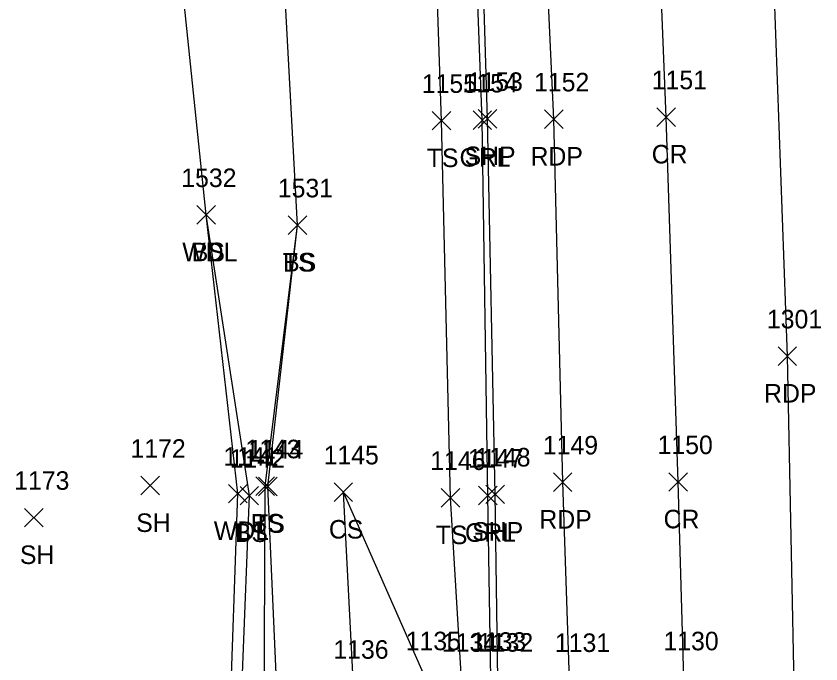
# Model space of a CAD drawing. Extents: x 1618262 to 1622220, y 273782 to 283685.
# Drawn here: x 1621992.5 to 1622079.3, y 282748.6 to 282818.4 of the extents above; entities that cross this region are included whole.
import ezdxf

# ---------------------------------------------------------------- set-up
doc = ezdxf.new("R2010")
doc.units = 0
for name, color, linetype in [('L_A', 7, 'Continuous'), ('L_I', 7, 'Continuous'), ('L_TIC', 7, 'Continuous'), ('LAWA', 7, 'Continuous'), ('LELB', 7, 'Continuous'), ('P_A', 7, 'Continuous'), ('P_I', 7, 'Continuous'), ('P_TIC', 7, 'Continuous'), ('PET', 7, 'Continuous'), ('PRC', 7, 'Continuous'), ('PSP', 7, 'Continuous'), ('R_A', 7, 'Continuous'), ('R_I', 7, 'Continuous'), ('R_TIC', 7, 'Continuous'), ('RGR', 7, 'Continuous')]:
    doc.layers.add(name, color=color, linetype=linetype)

msp = doc.modelspace()

# ---------------------------------------------------------------- linework, layer by layer
at = {"layer": 'L_TIC'}
for points in [[(1622037.366, 282806.145), (1622039.366, 282808.145)], [(1622039.366, 282806.145), (1622037.366, 282808.145)], [(1622012.003, 282795.989), (1622014.003, 282797.989)], [(1622014.003, 282795.989), (1622012.003, 282797.989)], [(1622012.003, 282795.989), (1622014.003, 282797.989)], [(1622014.003, 282795.989), (1622012.003, 282797.989)], [(1622021.846, 282794.877), (1622023.846, 282796.877)], [(1622023.846, 282794.877), (1622021.846, 282796.877)], [(1622021.846, 282794.877), (1622023.846, 282796.877)], [(1622023.846, 282794.877), (1622021.846, 282796.877)], [(1622005.964, 282766.79), (1622007.964, 282768.79)], [(1622007.964, 282766.79), (1622005.964, 282768.79)], [(1622018.347, 282766.736), (1622020.347, 282768.736)], [(1622020.347, 282766.736), (1622018.347, 282768.736)], [(1622018.651, 282766.692), (1622020.651, 282768.692)], [(1622020.651, 282766.692), (1622018.651, 282768.692)], [(1622026.782, 282766.08), (1622028.782, 282768.08)], [(1622028.782, 282766.08), (1622026.782, 282768.08)], [(1622026.782, 282766.08), (1622028.782, 282768.08)], [(1622028.782, 282766.08), (1622026.782, 282768.08)], [(1622015.402, 282765.923), (1622017.402, 282767.923)], [(1622017.402, 282765.923), (1622015.402, 282767.923)], [(1622016.648, 282765.711), (1622018.648, 282767.711)], [(1622018.648, 282765.711), (1622016.648, 282767.711)], [(1622038.334, 282765.475), (1622040.334, 282767.475)], [(1622040.334, 282765.475), (1622038.334, 282767.475)], [(1621993.426, 282763.336), (1621995.426, 282765.336)], [(1621995.426, 282763.336), (1621993.426, 282765.336)]]:
    msp.add_lwpolyline(points, dxfattribs=at)
at = {"layer": 'LAWA'}
msp.add_lwpolyline([(1622012.261, 282719.262), (1622015.512, 282741.117), (1622016.402, 282766.923), (1622013.003, 282796.989), (1622009.949, 282826.463), (1622001.868, 282858.825)], dxfattribs=at)
at = {"layer": 'LELB'}
for points in [[(1622031.53, 282480.209), (1622034.92, 282519.516), (1622036.308, 282559.668), (1622038.549, 282600.481), (1622040.575, 282634.794), (1622041.384, 282671.626), (1622041.057, 282708.261), (1622040.536, 282746.865), (1622039.334, 282766.475), (1622038.366, 282807.145), (1622036.997, 282847.689), (1622035.465, 282881.364), (1622030.123, 282906.905), (1622032.201, 282930.97)], [(1622011.792, 282703.523), (1622017.803, 282718.897), (1622019.25, 282742.062), (1622019.347, 282767.736), (1622022.846, 282795.877), (1622021.207, 282825.793), (1622021.001, 282858.668), (1622021.577, 282889.835), (1622019.372, 282916.251), (1622019.074, 282930.132)], [(1622006.83, 282701.587), (1622009.972, 282709.565), (1622013.354, 282718.948), (1622016.651, 282741.117), (1622017.648, 282766.711), (1622013.003, 282796.989)], [(1622011.792, 282703.523), (1622019.526, 282719.135), (1622020.798, 282741.845), (1622019.651, 282767.692), (1622022.846, 282795.877)], [(1622038.036, 282634.62), (1622038.492, 282672.044), (1622038.146, 282708.503), (1622036.634, 282747.032), (1622027.782, 282767.08)], [(1622029.212, 282715.273), (1622028.888, 282746.116), (1622027.782, 282767.08)]]:
    msp.add_lwpolyline(points, dxfattribs=at)
at = {"layer": 'P_TIC'}
for points in [[(1622042.312, 282806.356), (1622044.312, 282808.356)], [(1622044.312, 282806.356), (1622042.312, 282808.356)], [(1622049.471, 282806.305), (1622051.471, 282808.305)], [(1622051.471, 282806.305), (1622049.471, 282808.305)], [(1622061.59, 282806.537), (1622063.59, 282808.537)], [(1622063.59, 282806.537), (1622061.59, 282808.537)], [(1622074.649, 282780.747), (1622076.649, 282782.747)], [(1622076.649, 282780.747), (1622074.649, 282782.747)], [(1622050.427, 282767.15), (1622052.427, 282769.15)], [(1622052.427, 282767.15), (1622050.427, 282769.15)], [(1622062.87, 282767.185), (1622064.87, 282769.185)], [(1622064.87, 282767.185), (1622062.87, 282769.185)], [(1622043.138, 282765.852), (1622045.138, 282767.852)], [(1622045.138, 282765.852), (1622043.138, 282767.852)]]:
    msp.add_lwpolyline(points, dxfattribs=at)
at = {"layer": 'PET'}
for points in [[(1622055.389, 282357.789), (1622060.735, 282405.546), (1622064, 282439.097), (1622067.385, 282476.749), (1622069.453, 282501.975), (1622071.171, 282531.215), (1622072.586, 282558.991), (1622074.383, 282609.306), (1622075.404, 282650.493), (1622076.38, 282682.885), (1622076.73, 282709.495), (1622076.466, 282742.794), (1622075.649, 282781.747), (1622073.854, 282831.38), (1622072.41, 282861.117), (1622070.969, 282880.709), (1622069.108, 282909.864), (1622067.074, 282934.336)], [(1622031.404, 282363.078), (1622036.529, 282409.612), (1622039.656, 282443.455), (1622042.912, 282478.81), (1622045.922, 282518.248), (1622048.156, 282558.34), (1622049.907, 282599.505), (1622051.114, 282634.143), (1622051.904, 282670.586), (1622052.331, 282709.809), (1622052.148, 282746.848), (1622051.427, 282768.15), (1622050.471, 282807.305), (1622048.588, 282847.854), (1622046.49, 282883.042), (1622043.219, 282932.276)]]:
    msp.add_lwpolyline(points, dxfattribs=at)
at = {"layer": 'PRC'}
msp.add_lwpolyline([(1622043.286, 282360.387), (1622048.896, 282407.643), (1622051.69, 282440.973), (1622055.31, 282477.626), (1622057.865, 282516.742), (1622059.99, 282557.513), (1622061.585, 282597.203), (1622062.841, 282633.199), (1622063.878, 282668.538), (1622064.406, 282708.38), (1622064.503, 282747.028), (1622063.87, 282768.185), (1622062.59, 282807.537), (1622060.956, 282848.034), (1622058.907, 282883.676), (1622055.26, 282933.108)], dxfattribs=at)
at = {"layer": 'PSP'}
msp.add_lwpolyline([(1622024.53, 282364.695), (1622029.224, 282410.341), (1622032.133, 282444.404), (1622034.721, 282480.169), (1622038.065, 282518.937), (1622040.189, 282559.981), (1622041.775, 282599.797), (1622043.576, 282635.077), (1622043.931, 282671.705), (1622044.179, 282709.624), (1622044.427, 282746.882), (1622044.138, 282766.852), (1622043.312, 282807.356), (1622042.106, 282847.846), (1622040.006, 282882.115), (1622036.278, 282931.352)], dxfattribs=at)
at = {"layer": 'R_TIC'}
for points in [[(1622041.763, 282806.193), (1622043.763, 282808.193)], [(1622043.763, 282806.193), (1622041.763, 282808.193)], [(1622042.35, 282765.727), (1622044.35, 282767.727)], [(1622044.35, 282765.727), (1622042.35, 282767.727)]]:
    msp.add_lwpolyline(points, dxfattribs=at)
at = {"layer": 'RGR'}
msp.add_lwpolyline([(1622023.476, 282364.894), (1622028.185, 282410.184), (1622031.232, 282444.188), (1622033.737, 282480.242), (1622036.802, 282518.899), (1622039.036, 282560.065), (1622040.978, 282599.772), (1622042.921, 282635.171), (1622043.063, 282671.763), (1622043.615, 282709.363), (1622043.681, 282746.97), (1622043.35, 282766.727), (1622042.763, 282807.193), (1622041.251, 282847.718), (1622039.436, 282882.181), (1622035.129, 282907.981)], dxfattribs=at)

# ---------------------------------------------------------------- texts
at = {"layer": 'L_A'}
for s, p in [('TS', (1622036.776, 282802.145)), ('WDL', (1622010.42, 282791.989)), ('BS', (1622011.444, 282791.989)), ('TS', (1622021.255, 282790.877)), ('BS', (1622021.287, 282790.877)), ('SH', (1622005.452, 282762.79)), ('BS', (1622017.788, 282762.736)), ('TS', (1622018.061, 282762.692)), ('WDL', (1622013.819, 282761.923)), ('BS', (1622016.089, 282761.711)), ('CS', (1622026.223, 282762.08)), ('CS', (1622026.223, 282762.08)), ('TS', (1622037.743, 282761.475)), ('SH', (1621992.915, 282759.336))]:
    msp.add_text(s, height=2, dxfattribs=at).set_placement(p)
at = {"layer": 'L_I'}
for s, p in [('1155', (1622036.241, 282810.145)), ('1532', (1622010.31, 282799.989)), ('1532', (1622010.31, 282799.989)), ('1531', (1622020.72, 282798.877)), ('1531', (1622020.72, 282798.877)), ('1172', (1622004.838, 282770.79)), ('1143', (1622017.221, 282770.736)), ('1144', (1622017.525, 282770.692)), ('1141', (1622014.843, 282769.923)), ('1142', (1622015.522, 282769.711)), ('1145', (1622025.656, 282770.08)), ('1145', (1622025.656, 282770.08)), ('1146', (1622037.153, 282769.475)), ('1173', (1621992.301, 282767.336)), ('1135', (1622034.509, 282750.032)), ('1134', (1622038.41, 282749.865)), ('1136', (1622026.708, 282749.116))]:
    msp.add_text(s, height=2, dxfattribs=at).set_placement(p)
at = {"layer": 'P_A'}
for s, p in [('CR', (1622061.023, 282802.537)), ('SHP', (1622040.847, 282802.356)), ('RDP', (1622047.959, 282802.305)), ('RDP', (1622073.137, 282776.747)), ('RDP', (1622048.915, 282763.15)), ('CR', (1622062.303, 282763.185)), ('SHP', (1622041.673, 282761.852))]:
    msp.add_text(s, height=2, dxfattribs=at).set_placement(p)
at = {"layer": 'P_I'}
for s, p in [('1153', (1622041.186, 282810.356)), ('1152', (1622048.345, 282810.305)), ('1151', (1622061.031, 282810.537)), ('1301', (1622073.444, 282784.747)), ('1150', (1622061.658, 282771.185)), ('1149', (1622049.293, 282771.15)), ('1148', (1622042.012, 282769.852)), ('1132', (1622042.302, 282749.882)), ('1131', (1622050.59, 282749.848)), ('1130', (1622062.291, 282750.028))]:
    msp.add_text(s, height=2, dxfattribs=at).set_placement(p)
at = {"layer": 'R_A'}
for p in [(1622040.307, 282802.193), (1622040.894, 282761.727)]:
    msp.add_text('GRL', height=2, dxfattribs=at).set_placement(p)
at = {"layer": 'R_I'}
for s, p in [('1154', (1622040.638, 282810.193)), ('1147', (1622041.225, 282769.727)), ('1133', (1622041.555, 282749.97))]:
    msp.add_text(s, height=2, dxfattribs=at).set_placement(p)

doc.saveas('drawing.dxf')
